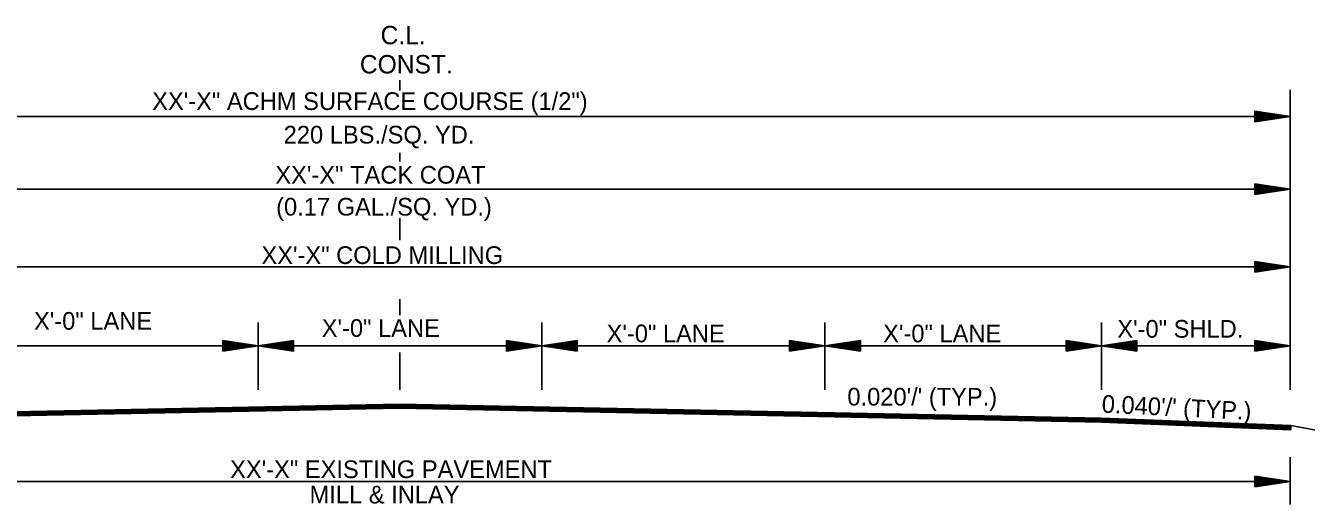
# Model space of a CAD drawing. Extents: x 544199 to 1930787, y -1968972 to 596640.
# Drawn here: x 551716 to 552259, y -1967595 to -1967392 of the extents above; entities that cross this region are included whole.
import ezdxf

# ---------------------------------------------------------------- set-up
doc = ezdxf.new("R2010")
doc.units = 0
doc.layers.add('R_Draft', color=7, linetype='Continuous')

msp = doc.modelspace()

# ---------------------------------------------------------------- linework, layer by layer
at = {"layer": 'R_Draft'}
for p, q in [((551874.24, -1967419.61), (551874.24, -1967415.2)), ((552236.71, -1967428.34), (552251.71, -1967430.59)), ((552236.71, -1967428.34), (552236.71, -1967432.84)), ((552236.71, -1967428.72), (552249.2, -1967430.59)), ((552236.71, -1967429.1), (552246.62, -1967430.59)), ((552236.71, -1967429.47), (552244.12, -1967430.59)), ((551494.06, -1967430.59), (552251.71, -1967430.59)), ((552236.71, -1967429.86), (552241.58, -1967430.59)), ((552236.71, -1967430.24), (552239.08, -1967430.59)), ((552236.71, -1967432.84), (552251.71, -1967430.59)), ((552236.71, -1967431.33), (552241.58, -1967430.59)), ((552236.71, -1967432.08), (552246.62, -1967430.59)), ((552236.71, -1967432.47), (552249.2, -1967430.59)), ((552236.71, -1967431.71), (552244.12, -1967430.59)), ((552236.71, -1967430.94), (552239.08, -1967430.59)), ((551874.24, -1967449.74), (551874.24, -1967446.07)), ((551494.06, -1967461.46), (552251.71, -1967461.46)), ((552236.71, -1967459.21), (552251.71, -1967461.46)), ((552236.71, -1967459.21), (552236.71, -1967463.71)), ((552236.71, -1967459.59), (552249.2, -1967461.46)), ((552236.71, -1967459.97), (552246.62, -1967461.46)), ((552236.71, -1967460.34), (552244.12, -1967461.46)), ((552236.71, -1967460.73), (552241.58, -1967461.46)), ((552236.71, -1967461.11), (552239.08, -1967461.46)), ((552236.71, -1967463.71), (552251.71, -1967461.46)), ((552236.71, -1967462.2), (552241.58, -1967461.46)), ((552236.71, -1967462.95), (552246.62, -1967461.46)), ((552236.71, -1967463.34), (552249.2, -1967461.46)), ((552236.71, -1967462.58), (552244.12, -1967461.46)), ((552236.71, -1967461.81), (552239.08, -1967461.46)), ((551874.24, -1967483.1), (551874.24, -1967473.8)), ((551494.06, -1967494.39), (552251.71, -1967494.39)), ((552236.71, -1967492.14), (552251.71, -1967494.39)), ((552236.71, -1967492.14), (552236.71, -1967496.64)), ((552236.71, -1967492.52), (552249.2, -1967494.39)), ((552236.71, -1967492.9), (552246.62, -1967494.39)), ((552236.71, -1967493.27), (552244.12, -1967494.39)), ((552236.71, -1967493.66), (552241.58, -1967494.39)), ((552236.71, -1967494.04), (552239.08, -1967494.39)), ((552236.71, -1967496.64), (552251.71, -1967494.39)), ((552236.71, -1967495.13), (552241.58, -1967494.39)), ((552236.71, -1967495.88), (552246.62, -1967494.39)), ((552236.71, -1967496.27), (552249.2, -1967494.39)), ((552236.71, -1967495.51), (552244.12, -1967494.39)), ((552236.71, -1967494.74), (552239.08, -1967494.39)), ((551874.24, -1967514.82), (551874.24, -1967508.17)), ((551814.24, -1967527.93), (551814.24, -1967518.04)), ((551814.24, -1967546.59), (551814.24, -1967518.04)), ((551934.5, -1967546.58), (551934.5, -1967518.03)), ((552054.5, -1967546.58), (552054.5, -1967518.03)), ((552171.71, -1967527.93), (552171.71, -1967518.03)), ((552171.71, -1967546.58), (552171.71, -1967518.03)), ((551799.24, -1967525.68), (551814.24, -1967527.93)), ((551799.24, -1967525.68), (551799.24, -1967530.18)), ((551799.24, -1967526.05), (551811.74, -1967527.93)), ((551799.24, -1967526.44), (551809.16, -1967527.93)), ((551799.24, -1967526.81), (551806.66, -1967527.93)), ((551799.24, -1967527.2), (551804.12, -1967527.93)), ((551829.24, -1967525.68), (551814.24, -1967527.93)), ((551829.24, -1967526.05), (551816.75, -1967527.93)), ((551829.24, -1967526.44), (551819.33, -1967527.93)), ((551829.24, -1967526.81), (551821.83, -1967527.93)), ((551829.24, -1967527.19), (551824.37, -1967527.93)), ((551829.24, -1967530.18), (551829.24, -1967525.68)), ((551919.5, -1967525.68), (551934.5, -1967527.93)), ((551919.5, -1967525.68), (551919.5, -1967530.18)), ((551919.5, -1967526.05), (551932, -1967527.93)), ((551919.5, -1967526.44), (551929.42, -1967527.93)), ((551919.5, -1967526.81), (551926.92, -1967527.93)), ((551919.5, -1967527.2), (551924.38, -1967527.93)), ((551949.5, -1967525.68), (551934.5, -1967527.93)), ((551949.5, -1967526.05), (551937.01, -1967527.93)), ((551949.5, -1967526.44), (551939.59, -1967527.93)), ((551949.5, -1967526.81), (551942.09, -1967527.93)), ((551949.5, -1967527.19), (551944.63, -1967527.93)), ((551949.5, -1967530.18), (551949.5, -1967525.68)), ((552039.5, -1967525.68), (552054.5, -1967527.93)), ((552039.5, -1967525.68), (552039.5, -1967530.18)), ((552039.5, -1967526.05), (552052, -1967527.93)), ((552039.5, -1967526.44), (552049.42, -1967527.93)), ((552039.5, -1967526.81), (552046.92, -1967527.93)), ((552039.5, -1967527.2), (552044.38, -1967527.93)), ((552069.5, -1967525.68), (552054.5, -1967527.93)), ((552069.5, -1967526.05), (552057, -1967527.93)), ((552069.5, -1967526.44), (552059.58, -1967527.93)), ((552069.5, -1967526.81), (552062.08, -1967527.93)), ((552069.5, -1967527.19), (552064.62, -1967527.93)), ((552069.5, -1967530.18), (552069.5, -1967525.68)), ((552156.71, -1967525.68), (552171.71, -1967527.93)), ((552156.71, -1967525.68), (552156.71, -1967530.18)), ((552156.71, -1967526.05), (552169.2, -1967527.93)), ((552156.71, -1967526.44), (552166.62, -1967527.93)), ((552156.71, -1967526.81), (552164.12, -1967527.93)), ((552156.71, -1967527.2), (552161.58, -1967527.93)), ((552186.71, -1967525.68), (552171.71, -1967527.93)), ((552186.71, -1967526.05), (552174.21, -1967527.93)), ((552186.71, -1967526.44), (552176.79, -1967527.93)), ((552186.71, -1967526.81), (552179.29, -1967527.93)), ((552186.71, -1967527.19), (552181.83, -1967527.93)), ((552186.71, -1967530.18), (552186.71, -1967525.68)), ((552236.71, -1967525.68), (552251.71, -1967527.93)), ((552236.71, -1967525.68), (552236.71, -1967530.18)), ((552236.71, -1967526.05), (552249.2, -1967527.93)), ((552236.71, -1967526.44), (552246.62, -1967527.93)), ((552236.71, -1967526.81), (552244.12, -1967527.93)), ((552236.71, -1967527.2), (552241.58, -1967527.93)), ((551814.24, -1967527.93), (551694.32, -1967527.93)), ((551799.24, -1967527.58), (551801.61, -1967527.93)), ((551799.24, -1967530.18), (551814.24, -1967527.93)), ((551799.24, -1967528.66), (551804.12, -1967527.93)), ((551799.24, -1967529.42), (551809.16, -1967527.93)), ((551799.24, -1967529.8), (551811.74, -1967527.93)), ((551799.24, -1967529.05), (551806.66, -1967527.93)), ((551799.24, -1967528.28), (551801.61, -1967527.93)), ((551814.24, -1967546.59), (551814.24, -1967527.93)), ((551934.5, -1967527.93), (551814.24, -1967527.93)), ((551829.24, -1967530.18), (551814.24, -1967527.93)), ((551814.24, -1967543.33), (551814.24, -1967530.04)), ((551829.24, -1967529.8), (551816.75, -1967527.93)), ((551829.24, -1967529.42), (551819.33, -1967527.93)), ((551829.24, -1967529.05), (551821.83, -1967527.93)), ((551829.24, -1967528.66), (551824.37, -1967527.93)), ((551829.24, -1967527.58), (551826.87, -1967527.93)), ((551829.24, -1967528.28), (551826.87, -1967527.93)), ((551874.24, -1967546.59), (551874.24, -1967530.73)), ((551919.5, -1967527.58), (551921.87, -1967527.93)), ((551919.5, -1967530.18), (551934.5, -1967527.93)), ((551919.5, -1967528.66), (551924.38, -1967527.93)), ((551919.5, -1967529.42), (551929.42, -1967527.93)), ((551919.5, -1967529.8), (551932, -1967527.93)), ((551919.5, -1967529.05), (551926.92, -1967527.93)), ((551919.5, -1967528.28), (551921.87, -1967527.93)), ((551934.5, -1967527.93), (552054.5, -1967527.93)), ((551949.5, -1967530.18), (551934.5, -1967527.93)), ((551949.5, -1967529.8), (551937.01, -1967527.93)), ((551949.5, -1967529.42), (551939.59, -1967527.93)), ((551949.5, -1967529.05), (551942.09, -1967527.93)), ((551949.5, -1967528.66), (551944.63, -1967527.93)), ((551949.5, -1967527.58), (551947.13, -1967527.93)), ((551949.5, -1967528.28), (551947.13, -1967527.93)), ((552039.5, -1967527.58), (552041.87, -1967527.93)), ((552039.5, -1967530.18), (552054.5, -1967527.93)), ((552039.5, -1967528.66), (552044.38, -1967527.93)), ((552039.5, -1967529.42), (552049.42, -1967527.93)), ((552039.5, -1967529.8), (552052, -1967527.93)), ((552039.5, -1967529.05), (552046.92, -1967527.93)), ((552039.5, -1967528.28), (552041.87, -1967527.93)), ((552051.71, -1967527.93), (552171.71, -1967527.93)), ((552069.5, -1967530.18), (552054.5, -1967527.93)), ((552069.5, -1967529.8), (552057, -1967527.93)), ((552069.5, -1967529.42), (552059.58, -1967527.93)), ((552069.5, -1967529.05), (552062.08, -1967527.93)), ((552069.5, -1967528.66), (552064.62, -1967527.93)), ((552069.5, -1967527.58), (552067.13, -1967527.93)), ((552069.5, -1967528.28), (552067.13, -1967527.93)), ((552156.71, -1967527.58), (552159.08, -1967527.93)), ((552156.71, -1967530.18), (552171.71, -1967527.93)), ((552156.71, -1967528.66), (552161.58, -1967527.93)), ((552156.71, -1967529.42), (552166.62, -1967527.93)), ((552156.71, -1967529.8), (552169.2, -1967527.93)), ((552156.71, -1967529.05), (552164.12, -1967527.93)), ((552156.71, -1967528.28), (552159.08, -1967527.93)), ((552171.71, -1967527.93), (552251.71, -1967527.93)), ((552186.71, -1967530.18), (552171.71, -1967527.93)), ((552186.71, -1967529.8), (552174.21, -1967527.93)), ((552186.71, -1967529.42), (552176.79, -1967527.93)), ((552186.71, -1967529.05), (552179.29, -1967527.93)), ((552186.71, -1967528.66), (552181.83, -1967527.93)), ((552186.71, -1967527.58), (552184.34, -1967527.93)), ((552186.71, -1967528.28), (552184.34, -1967527.93)), ((552236.71, -1967527.58), (552239.08, -1967527.93)), ((552236.71, -1967530.18), (552251.71, -1967527.93)), ((552236.71, -1967528.66), (552241.58, -1967527.93)), ((552236.71, -1967529.42), (552246.62, -1967527.93)), ((552236.71, -1967529.8), (552249.2, -1967527.93)), ((552236.71, -1967529.05), (552244.12, -1967527.93)), ((552236.71, -1967528.28), (552239.08, -1967527.93)), ((551874.24, -1967552.59), (551574.32, -1967558.59)), ((551874.25, -1967552.89), (551574.32, -1967558.89)), ((551874.26, -1967553.19), (551574.33, -1967559.19)), ((551874.26, -1967553.49), (551574.33, -1967559.49)), ((551874.27, -1967553.79), (551574.34, -1967559.79)), ((551874.27, -1967554.09), (551574.35, -1967560.09)), ((551874.28, -1967554.29), (551574.35, -1967560.29)), ((552171.68, -1967560.04), (551874.21, -1967554.09)), ((552171.67, -1967560.24), (551874.21, -1967554.29)), ((552171.68, -1967559.74), (551874.22, -1967553.79)), ((552171.69, -1967559.14), (551874.23, -1967553.19)), ((552171.69, -1967559.44), (551874.23, -1967553.49)), ((552171.71, -1967558.54), (551874.24, -1967552.59)), ((552171.7, -1967558.84), (551874.24, -1967552.89)), ((552171.66, -1967559.74), (552251.97, -1967562.95)), ((552171.67, -1967559.44), (552251.97, -1967562.65)), ((552171.68, -1967559.14), (552251.94, -1967562.35)), ((552171.69, -1967558.84), (552251.96, -1967562.05)), ((552171.71, -1967558.54), (552251.97, -1967561.75)), ((552171.64, -1967560.24), (552251.97, -1967563.46)), ((552171.65, -1967560.04), (552251.97, -1967563.26)), ((552251.97, -1967561.75), (552251.97, -1967563.45)), ((552251.97, -1967561.75), (552251.97, -1967563.46)), ((552251.97, -1967561.75), (552352.04, -1967580.13)), ((552251.71, -1967575.14), (552251.71, -1967595.14)), ((551494.06, -1967585.39), (552251.71, -1967585.39)), ((552236.71, -1967583.14), (552251.71, -1967585.39)), ((552236.71, -1967583.14), (552236.71, -1967587.64)), ((552236.71, -1967583.52), (552249.2, -1967585.39)), ((552236.71, -1967583.9), (552246.62, -1967585.39)), ((552236.71, -1967584.28), (552244.12, -1967585.39)), ((552236.71, -1967584.67), (552241.58, -1967585.39)), ((552236.71, -1967585.04), (552239.08, -1967585.39)), ((552236.71, -1967587.64), (552251.71, -1967585.39)), ((552236.71, -1967586.13), (552241.58, -1967585.39)), ((552236.71, -1967586.89), (552246.62, -1967585.39)), ((552236.71, -1967587.27), (552249.2, -1967585.39)), ((552236.71, -1967586.51), (552244.12, -1967585.39)), ((552236.71, -1967585.75), (552239.08, -1967585.39))]:
    msp.add_line(p, q, dxfattribs=at)
msp.add_lwpolyline([(552251.71, -1967419.33), (552251.71, -1967546.58)], dxfattribs=at)

# ---------------------------------------------------------------- texts
for s, height, p in [('C.L.', 7.8, (551866.14, -1967400)), ('CONST.', 7.8, (551857.36, -1967412.37)), ('XX\'-X" ACHM SURFACE COURSE (1/2")', 7.5, (551769.33, -1967427.86)), ('220 LBS./SQ. YD. ', 7.5, (551825.07, -1967442.09)), ('XX\'-X" TACK COAT', 7.5, (551821.53, -1967459.11)), ('(0.17 GAL./SQ. YD.)', 7.5, (551821.88, -1967472.65)), ('XX\'-X" COLD MILLING', 7.5, (551815.64, -1967493.18)), ('X\'-0" LANE', 7.5, (551719.25, -1967521.06)), ('X\'-0" LANE', 7.5, (551841.2, -1967524.09)), ('X\'-0" LANE', 7.5, (551961.95, -1967526.39)), ('X\'-0" LANE', 7.5, (552079.15, -1967526.39)), ('X\'-0" SHLD.', 7.5, (552178.4, -1967524.44)), ('XX\'-X" EXISTING PAVEMENT', 7.5, (551802.36, -1967583.99)), ('MILL & INLAY', 7.5, (551836.05, -1967594.73))]:
    msp.add_text(s, height=height, dxfattribs=at).set_placement(p)
for s, rotation, p in [("0.020'/' (TYP.)", 360, (552064, -1967553.22)), ("0.040'/' (TYP.)", 357.1939, (552171.66, -1967556.2))]:
    msp.add_text(s, height=7.5, rotation=rotation, dxfattribs=at).set_placement(p)

doc.saveas('drawing.dxf')
